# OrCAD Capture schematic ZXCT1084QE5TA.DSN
size Custom; title: ZXCT1084Q - PRECISION HIGH VOLTAGE HIGH-SIDE CURRENT MONITORS; rev: 1.0; note: DS37015  Rev. 1 - 2
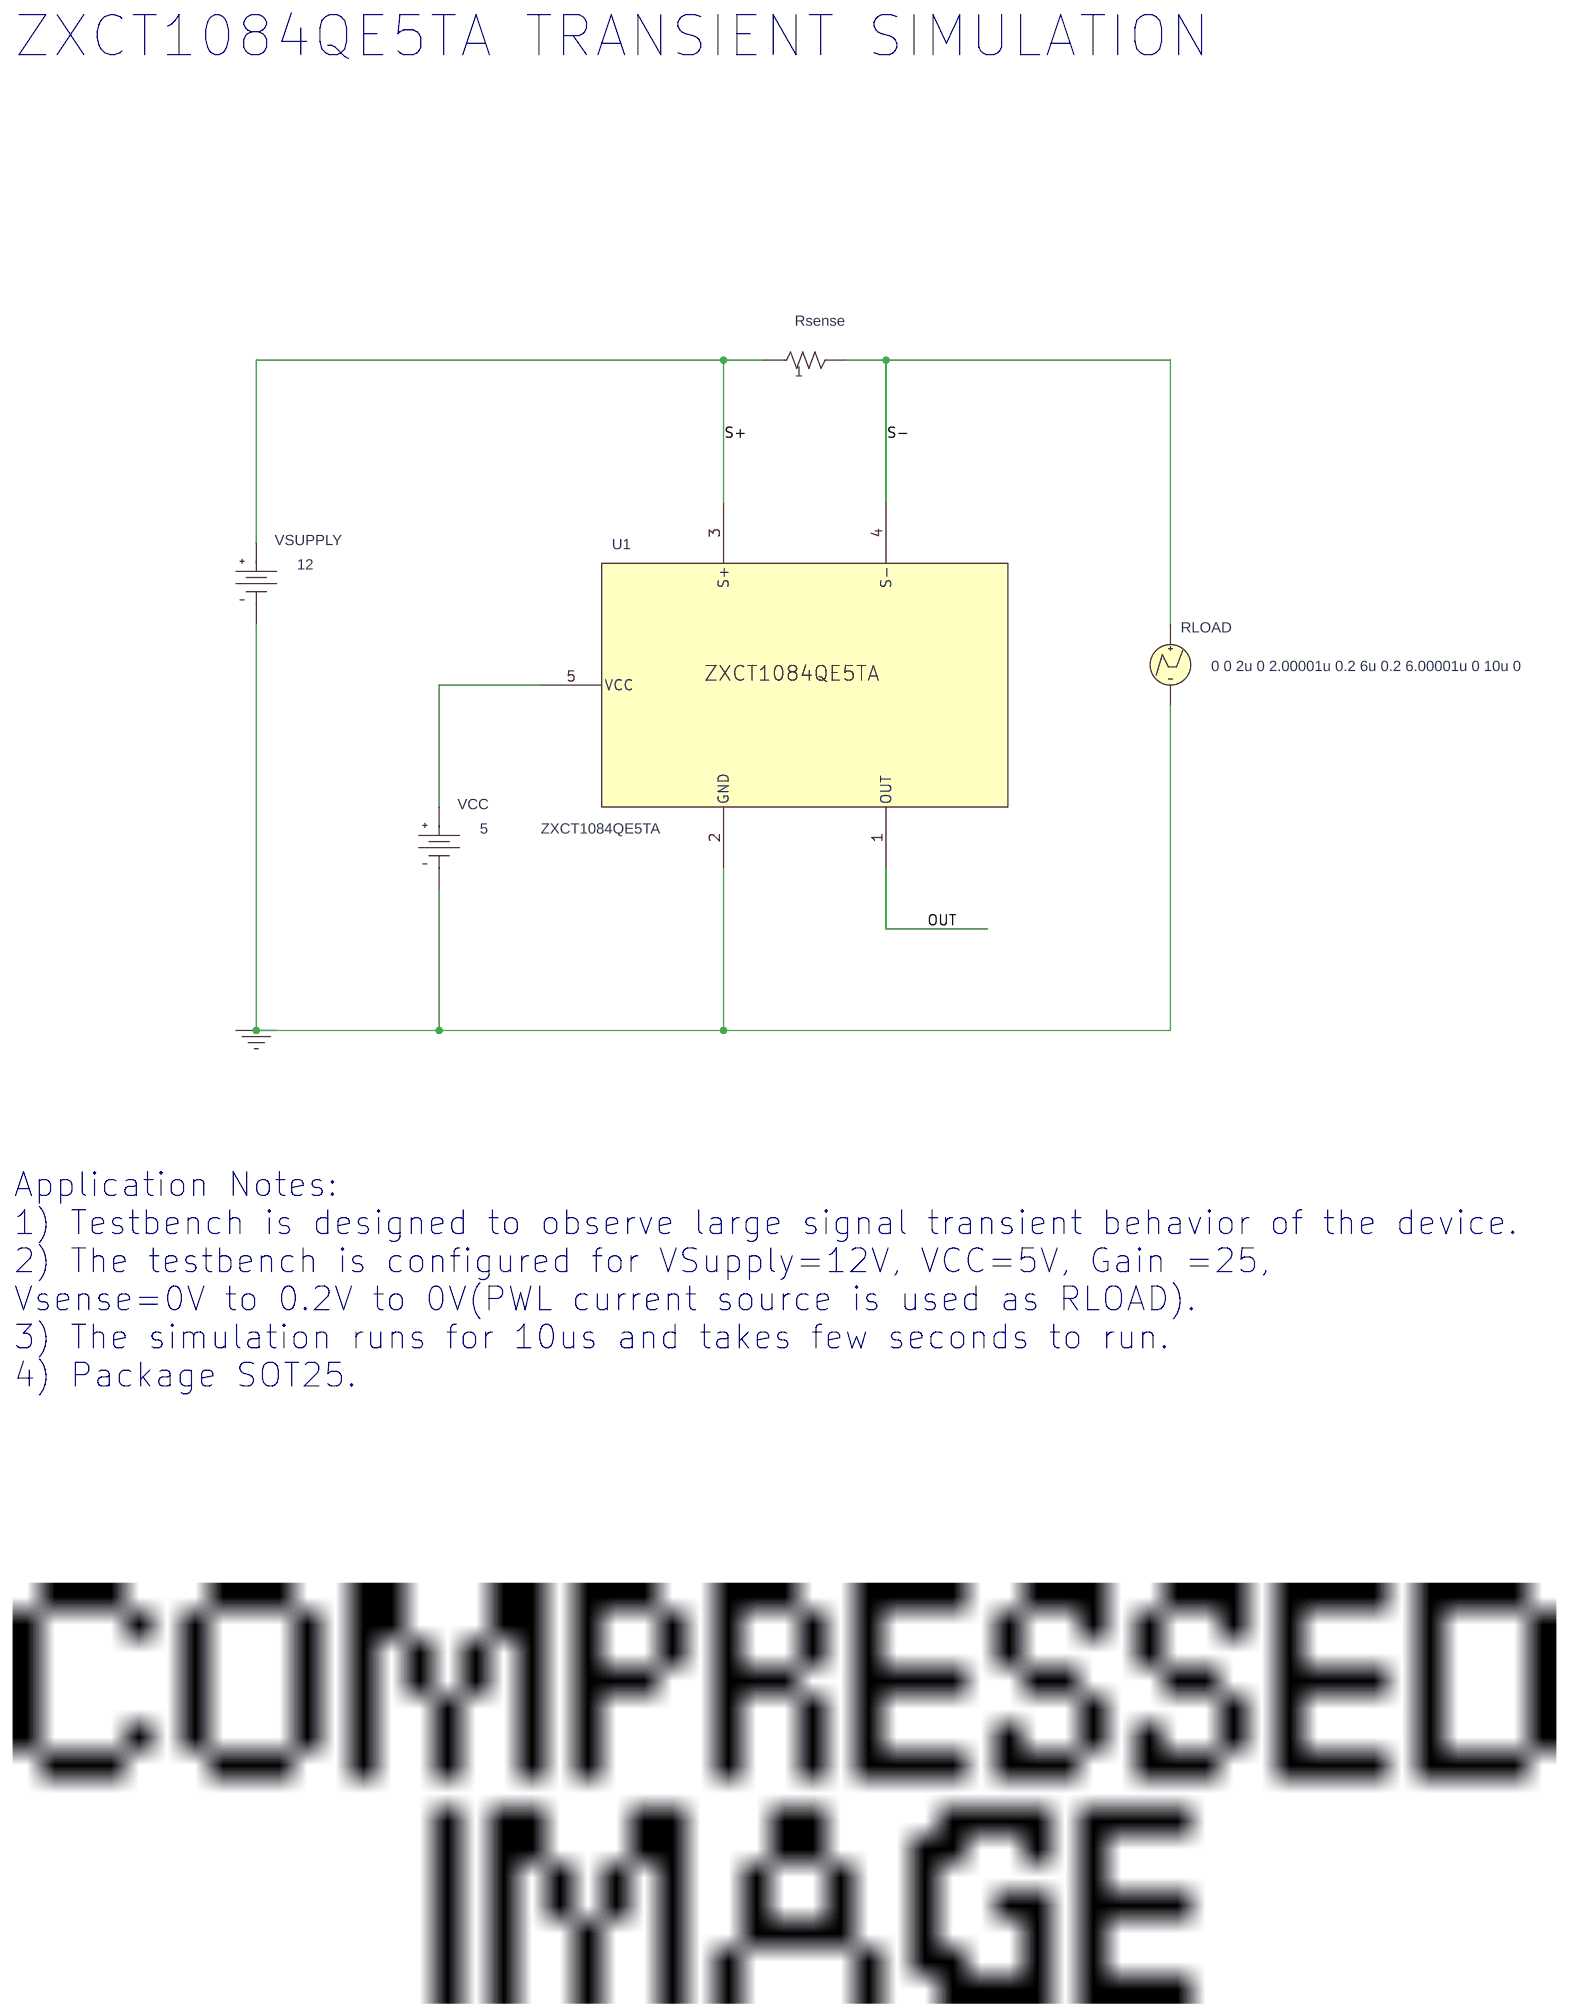
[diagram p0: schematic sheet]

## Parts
RLOAD  IPWL_GENERIC
Rsense  1  [AX/RC05]
U1  ZXCT1084QE5TA
VCC  VDC
VSUPPLY  VDC

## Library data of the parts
RLOAD = IPWL_GENERIC: AppProp: No_reps$POINTS_TYPE_PWL$0$0; FIRST_NPAIRS: 0 0 2u 0 2.00001u 0.2 6u 0.2 6.00001u 0 10u 0; PSpiceTemplate: I^@REFDES %+ %- ?DC|DC @DC| ?AC|AC @AC| PWL ?TSF|TIME_SCALE_FACTOR=@TSF| ?VSF|VALUE_SCALE_FACTOR=@VSF| ?REPEAT_VALUE| \n+ REPEAT FOR @REPEAT_VALUE| \n+ @FIRST_NPAIRS ?SECOND_NPAIRS|\n+ @SECOND_NPAIRS ?THIRD_NPAIRS/\n+ @THIRD_NPAIRS/| ?REPEAT_VALUE| \n+ ENDREPEAT|
Rsense = R
U1 = ZXCT1084QE5TA_1
VCC = VDC: DC: 5
VSUPPLY = VDC: DC: 12

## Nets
0: RLOAD.2(-) U1.2(GND) VCC.1(-) VSUPPLY.1(-)
OUT: U1.1(OUT)
S+: Rsense.1 U1.3(S+) VSUPPLY.0(+)
S-: RLOAD.1(+) Rsense.2 U1.4(S-)
N107339: U1.5(VCC) VCC.0(+)

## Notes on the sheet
- ZXCT1084QE5TA TRANSIENT SIMULATION
- Application Notes:
  1) Testbench is designed to observe large signal transient behavior of the device.
  2) The testbench is configured for VSupply=12V, VCC=5V, Gain =25,
  Vsense=0V to 0.2V to 0V(PWL current source is used as RLOAD).
  3) The simulation runs for 10us and takes few seconds to run.
  4) Package SOT25.
